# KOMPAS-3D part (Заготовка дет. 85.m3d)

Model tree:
1. Копирование:2  (labels: Копия тела : Тело 1)
2. Эскиз:1
3. Операция вращения:1
     Угол 1 = 360
4. Скругление:1
     Радиус = 2
5. Скругление:2  (with: Сечение модели:1)
     Радиус = 3

Referenced files in C:\Users\andrey\Desktop\Заказ 1793547 (Черч)\Дет. 85\: Деталь 85.m3d
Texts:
  Копия тела : Тело 1
  Точка начала. Х
  Точка начала. Y
  Точка начала. Z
